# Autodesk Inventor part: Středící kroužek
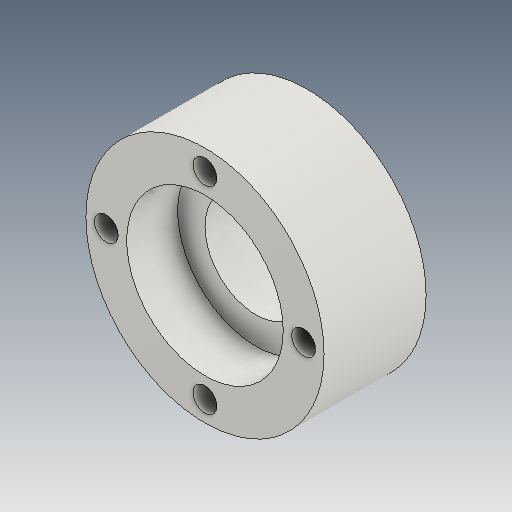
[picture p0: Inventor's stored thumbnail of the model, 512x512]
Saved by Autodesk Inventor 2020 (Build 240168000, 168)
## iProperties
Created: 2025-03
Part Number: Středící kroužek
Material: Ocel
Document SubType Name: Modeling
Designer: doma
Density: 7.85 g/cm^3
Appearance: Ocel
Mass: 591.136 g
Surface Area: 187.93 cm^2
Volume: 75.304 cm^3
Author: doma
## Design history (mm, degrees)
sketch "Náčrt1"
  geometry: C1 r 35 at (0, 0); 1 further point
  constraints: 1 centre point, 1 coincident
  dimensions: "d0" = 70 diameter of C1
extrude "Vysunutí1" new body sketch "Náčrt1" distance "d1" = 30; taper "d2" = 0 deg
sketch "Náčrt2"
  geometry: C1 r 3.5 at (0, 29); C2 r 3.5 at (-29, 0); C3 r 3.5 at (0, -29); C4 r 3.5 at (29, 0); 1 further point
  constraints: 4 centre point, 9 other
  dimensions: "d4" = 7 diameter of C1; "d5" = 29 distance of point (0, 0) C1.centre; "d8" = 360 deg dimension on point (0, 0) C1.centre (derived)
extrude "Vysunutí2" cut sketch "Náčrt2" extent not by distance; stored distance "d10" = 0; taper "d11" = 0 deg
sketch "Náčrt3"
  geometry: C1 r 23 at (0, 0); 1 further point
  constraints: 1 centre point, 1 coincident
  dimensions: "d13" = 46 diameter of C1
extrude "Vysunutí3" cut sketch "Náčrt3" distance "d14" = 15; taper "d15" = 0 deg
sketch "Náčrt4"
  geometry: C1 r 15 at (0, 0); 1 further point
  constraints: 1 centre point, 1 coincident
  dimensions: "d16" = 30 diameter of C1
extrude "Vysunutí4" cut sketch "Náčrt4" extent not by distance; stored distance "d17" = 0; taper "d18" = 0 deg
node "Těleso1"
